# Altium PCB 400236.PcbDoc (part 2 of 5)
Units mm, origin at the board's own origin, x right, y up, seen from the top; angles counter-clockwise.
Board outline 136.53 x 63.5 mm, 4 copper layers (Top Layer, Mid-Layer 1, Mid-Layer 2, Bottom Layer), stack 1.49 mm thick; 344 components, 236 nets, 1364 pads, 1393 vias.
Unrouted connection lines stored in the file: 6.
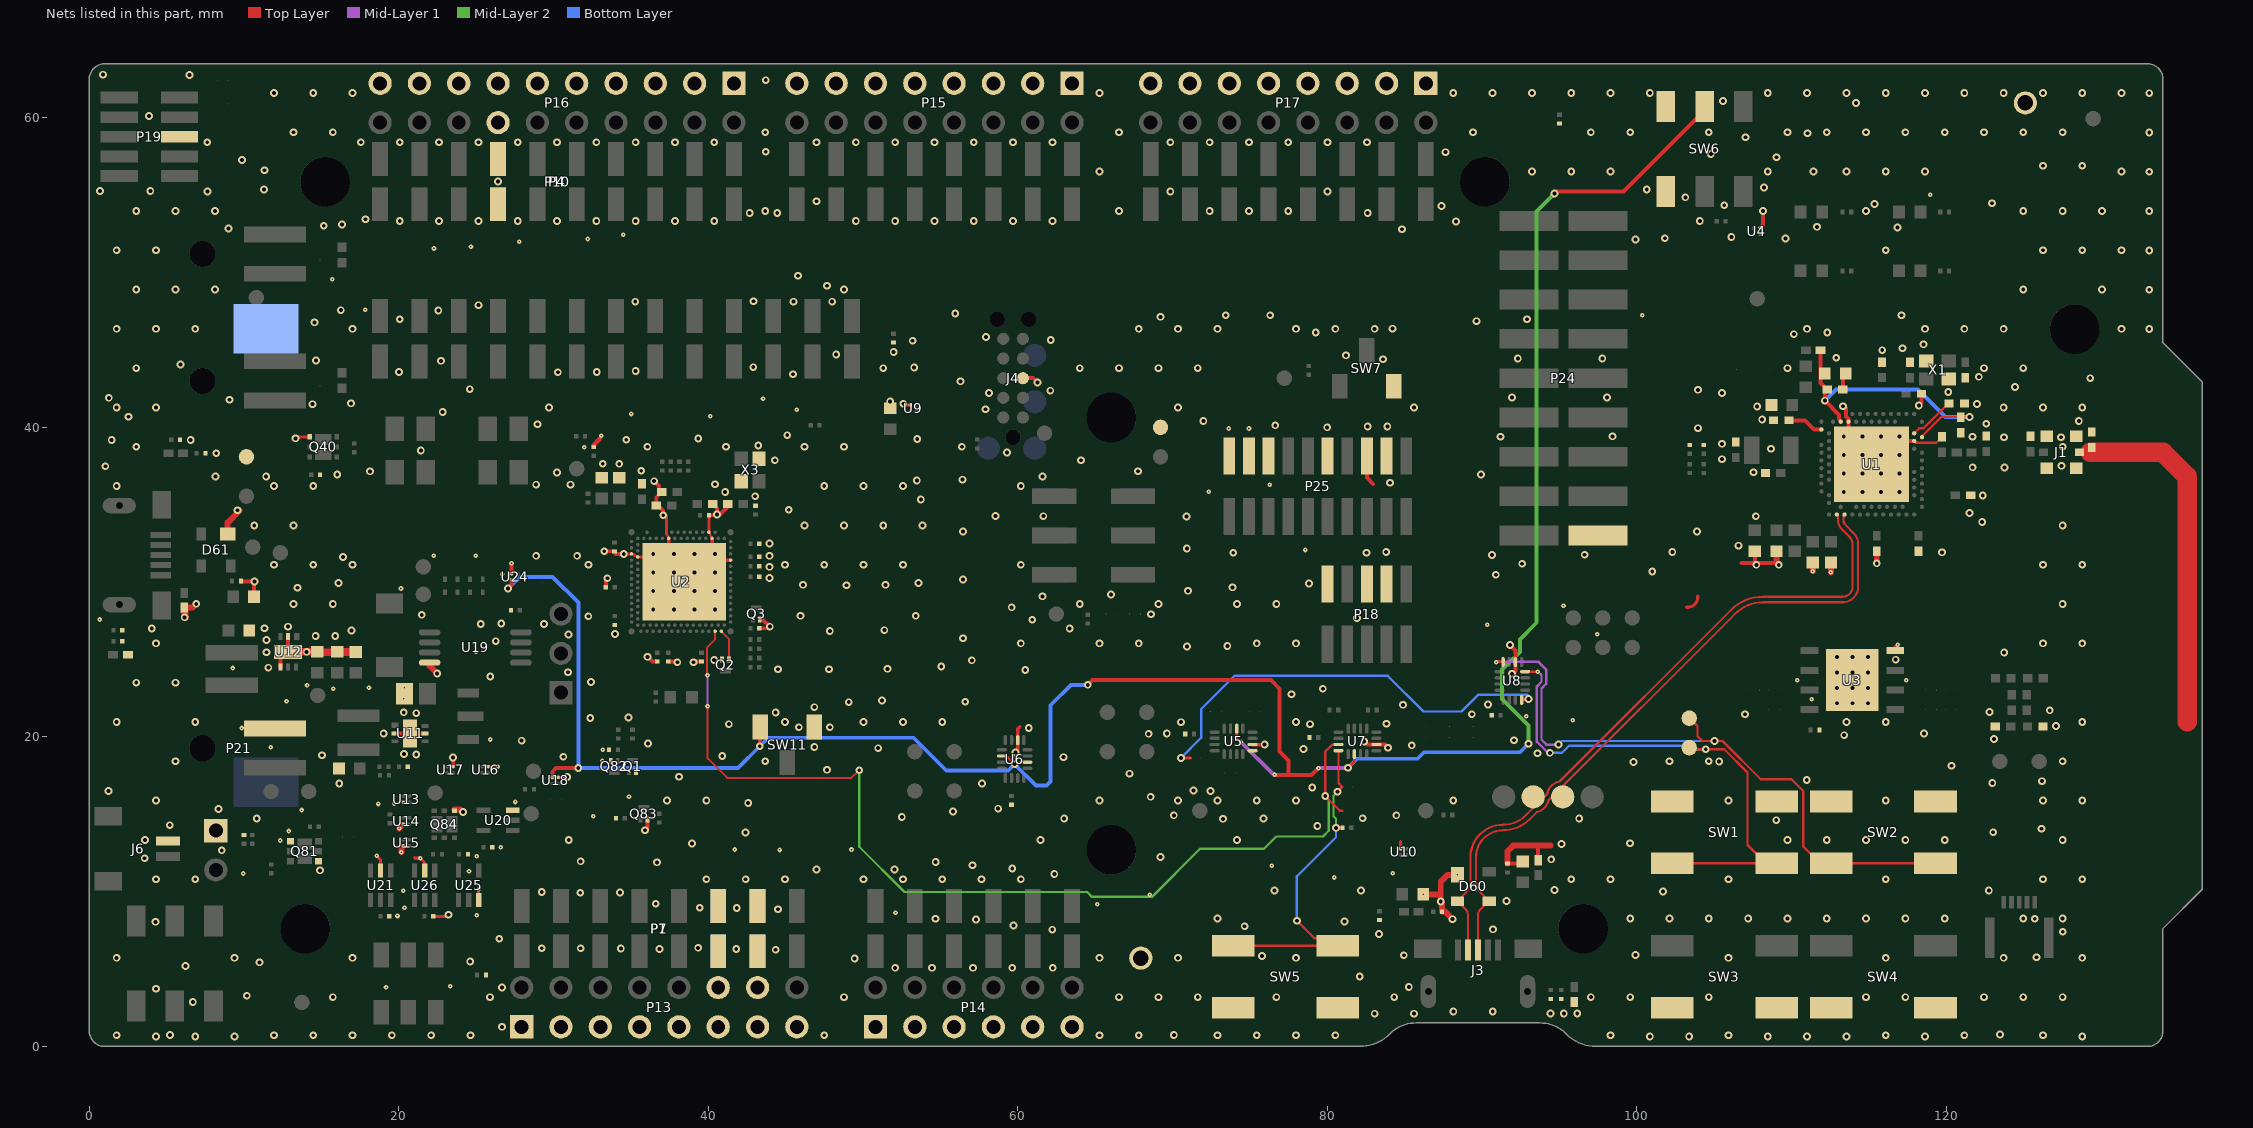
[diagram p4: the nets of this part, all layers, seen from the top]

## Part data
Bat1: library part "Bat Holder L-KLS5-CR2032-23-B1", "Bat Holder CR2032 SMD", Manufacturer="KLS Electronic", Manufacturer Part Number=L-KLS5-CR2032-23-B1, Part number IPS=N.A., Part number NEMS=100500651
C1 C2 C17 C18: library part C0402-12p, "Capacitor, NP0, ±2%", Manufacturer=N.A., Part number IPS=00000002398, Part number NEMS=100200137
C3: library part C0402-0.8p, "Capacitor, NP0, ±5%", Manufacturer=N.A., Part number IPS=00000007782, Part number NEMS=100200116
C4: library part C0402-0.5p, "Capacitor, C0G, ±0.05pF, 50V", Manufacturer=N.A., Part number IPS=00000004293, Part number NEMS=100200112
C5 C7 C8 C12: library part C0402-100n, "Capacitor, X7R, ±10%", Manufacturer=N.A., Part number IPS=00000005296, Part number NEMS=100200184
C6 C20 C38: library part C0603-4µ7-6.3V-X7R, "Capacitor, X7R, ±10%, 6.3V", Manufacturer="Samsung Electro-Mechanics America", Manufacturer Part Number=CL10B475KQ8NQNC, Part number IPS=00000002541, Part number NEMS=100200350, Part number Norautron=N.A., Supplier Part Number 1=1276-2087-1-ND
C9 C10 C13 C22: library part C0402-N.C., "Not mounted", Manufacturer=N.A., Part number NEMS=100200105
C11: library part C0402-100p, "Capacitor, NP0, ±5%", Manufacturer=N.A., Part number IPS=00000002361, Part number NEMS=100200148
C14 C15 C91 C92: library part C0603-1µ0, "Capacitor, X7R, ±10%", Manufacturer=N.A., Part number IPS=00000000616, Part number NEMS=100200271, Part number Norautron=262083409
C16: library part C0402-47n, "Capacitor, X7R, ±10%, 25V", Manufacturer=N.A., Part number IPS=00000003143, Part number NEMS=100200180
C19 C21 C37: library part C0603-4µ7-10V-X7S, "Capacitor, X7S, ±10%, 10V", Manufacturer=N.A., Part number IPS=00000001779, Part number NEMS=100200351, Supplier Part Number 1=445-14258-1-ND
C23: library part C0402-1.2p, "Capacitor, NP0, ±0.1pF", Manufacturer=N.A., Part number IPS=00000005410, Part number NEMS=100200119
C24 C25 C26 C27 C31 C32 C33 C34 C39 C42 C45 C48 C49 C50 C62 C65 C68 C69 C85 C89 C90 C93 C94: library part C0201-100n, "Capacitor, X5R, ±10%", Manufacturer=N.A., Part number IPS="00000001248, 00000002505", Part number NEMS=100200078, Part number Norautron=262071862
C28 C29 C35 C36 C40: library part C0402-1µ0-6.3V-X5R-10%, "Capacitor, X5R, ±10%, 6.3V", Manufacturer=N.A., Part number NEMS=100200498, Part number Norautron=26207137
C30: library part C0201-2n2, "Capacitor, X7R, ±10%, 10V", Manufacturer=N.A., Part number IPS=00000001778, Part number NEMS=100200060, Part number Norautron=26470002
C46 C47: library part C0402-300p, "Capacitor, C0G, ±5%, 50V", Manufacturer=N.A., Part number IPS=00000007788, Part number NEMS=100200155, Supplier Part Number 1=490-3234-1-ND
C51 C52: library part C0201-N.C., "Not mounted", Manufacturer=N.A., Part number NEMS=100200001
C53 C60 C63: library part C0201-10n, "Capacitor, X7R, ±10%", Manufacturer=N.A., Part number IPS=00000003480, Part number NEMS=100200067, Part number Norautron=26621779
C61 C64: library part C0603-10µ, "Capacitor, X5R, ±20%", Manufacturer=N.A., Part number IPS=00000007785, Part number NEMS=100200275
C66 C67: library part C0201-4n7, "Capacitor, X7R, ±10%, 10V", Manufacturer=N.A., Part number IPS=00000001243, Part number NEMS=100200063
C80 C82 C83 C88: library part C0603-10µ-25V-X5R-CL10A106MA8NRNC, "Capacitor, X5R, ±20%, 25V", Manufacturer="Samsung Electro-Mechanics America", Manufacturer Part Number=CL10A106MA8NRNC, Part number IPS=00000009948, Part number NEMS=100200354, Part number Norautron=N.A., Supplier Part Number 1=1276-1869-1-ND
C86: library part C0805-4µ7, "Capacitor, X5R, ±10%, 16V", Manufacturer=N.A., Part number IPS=00000006289, Part number NEMS=100200284
C87: library part C0201-150p-25V-COG-GRM0335C1E151JA01D, "Capacitor, NP0, ±5%, 25V", Manufacturer=N.A., Part number IPS=00000004306, Part number NEMS=100200444
C96: library part C0603-N.C., "Not mounted", Manufacturer=N.A., Part number NEMS=100200195
D60 D61: "Ultra low capacitance double rail-to-rail ESD protection diode", Manufacturer="NXP Semiconductors", Part number IPS=00000009951, Part number NEMS=101300082, Part number Norautron=26313940, Supplier Part Number 1=568-4140-1-ND
D80 D81 D82 D83: "20V schottky barrier diode, Vf 350 mV @ 100 mA, Ir 2.0 µA @ 10 V, If 500 mA", Manufacturer="ON Semiconductor", Part number IPS=00000009952, Part number NEMS=101300131, Part number Norautron=26311081, Supplier Part Number 1=NSR0620P2T5GOSCT-ND
D84: "Diode Schottky Vf=0.45, Vr=40V, If=1A, Ir=1µA", Manufacturer="Good-Ark Semiconductor", Part number IPS=N.A., Part number NEMS=101300212, Supplier Part Number 1=4786-LS14CT-ND
FB60 FB61 FB62 FB63 FB64 FB65: library part FB0402-120R@100M-500mA, "Ferrite Bead, 120 Ohm @ 100MHz, 500mA, 250 mOhm Max", Manufacturer=Murata, Manufacturer Part Number=BLM15AG121SN1D, Part number IPS=00000009954, Part number NEMS=100300099, Part number Norautron=265230631, Supplier Part Number 1=490-1005-1-ND
Fid1 Fid2: library part Fid-Mark, "Fiducial Mark", Manufacturer=N.A., Part number NEMS=100500073
J1: "Coaxial Connector with Switch", Manufacturer=Murata, Part number IPS=00000009955, Part number NEMS=100500400, Part number Norautron=26030338, Supplier Part Number 1=490-4981-1-ND
J2 J3: library part USB-Micro-B-RA-SMD-PiP, "MicroUSB-B-SMT", Manufacturer="Allen Creations Corp.", Manufacturer Part Number=AJU55-BS2111-L, Part number IPS=00000007790, Part number NEMS=100500490, Part number Norautron=N.A.
J4: library part TC2050-IDC-NLFP, "CBL PLUG-OF-NAILS 10-PIN", Manufacturer="Tag-Connect LLC", Part number IPS=N.A., Part number NEMS=100500463, Supplier Part Number 1=TC2050-IDC-NL-ND
J5: library part FPC_05P-0.5mm-RA-SMD, "0.5mm FPC, 5P,Right Angle SMT,Double Contact,H=1.2mm,White, Tin plated", Manufacturer=WCON, Manufacturer Part Number=5141-05RZDNWR03, Part number IPS=N.A., Part number NEMS=100500528
J6: library part SM02B-SRSS-TB, "1.0mm pitch connector side entry SMD", Manufacturer="JST Sales America Inc.", Manufacturer Part Number=SM02B-SRSS-TB(LF)(SN), Part number IPS=00000007791, Part number NEMS=100500383, Part number Norautron=N.A.
L1: library part L0402-4n7-LQG15HS4N7B02D, "Inductor, 700mA, ±0.1nH, 160mR LQG", Manufacturer=Murata, Manufacturer Part Number=LQG15HS4N7B02D, Part number IPS=N.A., Part number NEMS=100300410, Supplier Part Number 1=490-LQG15HS4N7B02DTR-ND
L2 L4: library part L0603-10µ-TDK, "Inductor, 250mA, ±20%, 1.05ohm. -55°C ~ 125°C", Manufacturer="TDK Corporation", Manufacturer Part Number=MLZ1608M100WTD25, Part number IPS=N.A., Part number NEMS=100300079, Part number Norautron=26521771, Supplier Part Number 1=445-175588-1-ND
L3: library part L0402-15n-LQG15HS15NJ02D, "Inductor, 450mA, ±5%,  0.32ohm", Manufacturer=Murata, Manufacturer Part Number=LQG15HS15NJ02D, Part number IPS=N.A., Part number NEMS=100300412, Supplier Part Number 1=490-2625-2-ND
L80: library part VLS3012HBX-4R7M-N, "4.7µH Shielded Wirewound Inductor 2.23A 201 mOhm Max Nonstandard", Manufacturer="TDK Corporation", Part number IPS=N.A., Part number NEMS=100300407, Supplier Part Number 1=445-VLS3012HBX-4R7M-NTR-ND
L81: library part NR3015-4µ7-1.04A-144mOhm, "Ferrite Inductor, Shielded, 1,04A, 144mOhm", Manufacturer="Taiyo Yuden", Manufacturer Part Number=NR3015T4R7M, Part number IPS=00000009960, Part number NEMS=100300145, Part number Norautron=N.A., Supplier Part Number 1=587-1649-1-ND
LED1 LED2 LED3 LED4 LED5: library part "VS 25C7M5", "LED, Green, 0603, 573nm, Vf=2.0V, 24mcd, - 40 to +85°C", Manufacturer="Victory Electronics", Part number IPS="00000001274, 00000009961", Part number NEMS=101400097, Part number Norautron=26313411, Supplier Part Number 1=N.A.
P1 P3 P6: library part "Socket 1x8 SMD", "Socket 1x8, 2.54mm (100mil), SMD", Manufacturer=WCON, Manufacturer Part Number=2171-108MS0CUNR3, Part number IPS=N.A., Part number NEMS=100500412
P2: library part "Socket 1x6 SMD", "Socket 1x6, 2.54mm (100mil), SMD", Manufacturer=WCON, Manufacturer Part Number=2171-106MS0CUNR3, Part number IPS=N.A., Part number NEMS=100500408
P4: library part "Socket 1x10 SMD", "Socket 1x10, 2.54mm (100mil), SMD", Manufacturer=WCON, Manufacturer Part Number=2171-110MS0CUNR3, Part number IPS=N.A., Part number NEMS=100500416
P5: library part "Pin Header 2x3 SMD", "Pin Header 2x3, 2.54mm (100mil) SMD", Manufacturer=WCON, Manufacturer Part Number=1125-1203S0M116CR03, Part number IPS=N.A., Part number NEMS=100500242
P7 P9 P12: library part "Pin List 1x8 SMD, N.C.", "Pin List 1x8, 2.54mm (100mil), SMD", Manufacturer=WCON, Manufacturer Part Number=1125-1108S0M116CR04, Part number IPS=N.A., Part number NEMS=100500330
P8: library part "Pin List 1x6 SMD, N.C.", "Pin List 1x6, 2.54mm (100mil), SMD", Manufacturer=WCON, Manufacturer Part Number=1125-1106S0M116R2, Part number IPS=N.A., Part number NEMS=100500321
P10: library part "Pin List 1x10 SMD, N.C.", "Pin List 1x10, 2.54mm (100mil), SMD", Manufacturer=WCON, Manufacturer Part Number=1125-1110S0M116R2, Part number IPS=N.A., Part number NEMS=100500338
P11: library part "Socket 2x3 SMD, N.C.", "Socket 2x3, 2.54mm (100mil), SMD", Manufacturer=WCON, Manufacturer Part Number=2171-203MS0CUNR3, Part number IPS=N.A., Part number NEMS=100500434
P13 P15 P17: library part "Pin Header 2x8, N.C.", "Pin Header 2x8, 2.54mm (100mil)", Manufacturer=N.A., Part number NEMS=100500270
P14: library part "Pin Header 2x6, N.C.", "Pin Header 2x6, 2.54mm (100mil)", Manufacturer=N.A., Part number NEMS=100500265
P16: library part "Pin Header 2x10, N.C.", "Pin Header 2x10, 2.54mm (100mil)", Manufacturer=N.A., Part number NEMS=100500274
P18 P19: library part "Pin Header 2x5 SMD, 1.27mm, KS", "Pin Header 2x5, 1.27mm (50mil), SMD, Keying Shroud", Manufacturer=WCON, Manufacturer Part Number=3132-10MS0BK00R5, Part number IPS=N.A., Part number NEMS=100500261
P20: library part "Pin List 1x13 SMD", "Pin List 1x13, 2.54mm (100mil), SMD", Manufacturer=WCON, Manufacturer Part Number=1125-1113S0M116CR04, Part number IPS=N.A., Part number NEMS=100500345
P21 P22 P23: library part "Pin List Ang 1x2 SMD, 2.54mm", "Pin List 1x2, 2.54mm (100mil), Right Angled, SMD", Manufacturer=WCON, Manufacturer Part Number=1125B-1102S0Z135CR06, Part number IPS=N.A., Part number NEMS=100500354
P24: library part "Socket 2x9 SMD", "Socket 2x9, 2.54mm (100mil), SMD", Manufacturer=WCON, Manufacturer Part Number=2171-209MS0CUNR3, Part number IPS=N.A., Part number NEMS=100500440
P25: library part "Pin Header 2x10 SMD, 1.27mm, KS, N.C.", "Pin Header 2x10, 1.27mm (50mil), SMD, Keying Shroud", Manufacturer=WCON, Manufacturer Part Number=3132-20MS0BK00R1, Part number IPS=N.A., Part number NEMS=100500279
P26: library part "Socket 1x13 SMD, N.C.", "Socket 1x13, 2.54mm (100mil), SMD", Manufacturer=WCON, Manufacturer Part Number=2171-113MS0CUNR1, Part number IPS=N.A., Part number NEMS=100500422
P27: library part "Pin List 1x2, N.C.", "Pin List 1x2, 2.54mm (100mil)", Manufacturer=N.A., Part number NEMS=100500298
P28: library part "Pin List 1x3, N.C.", "Pin List 1x3, 2.54mm (100mil)", Manufacturer=N.A., Part number NEMS=100500305
Q1 Q2 Q3 Q82 Q83: "N-Channel MOSFET, 20V, 1A, 470mOhm, 400mW", Manufacturer="Rohm Semiconductor", Part number IPS=00000009976, Part number NEMS=101300132, Part number Norautron=26320026, Supplier Part Number 1=RV2C010UNT2LCT-ND
Q40 Q84: library part PMCPB5530X,115, "Mosfet Array N and P-Channel 20V 4A (Ta), 3.4A (Ta) 490mW Surface Mount 6-HUSON-EP (2x2)", Manufacturer=Nexperia, Part number IPS=00000001918, Part number NEMS=101300165, Part number Norautron=N.A., Supplier Part Number 1=1727-1327-1-ND
Q80: "45V NPN high gain power transistor", Manufacturer="Diodes Incorporated", Part number IPS=00000009974, Part number NEMS=101300130, Part number Norautron=N.A., Supplier Part Number 1=FCX690BCT-ND
Q81: "Dual N Ch MOFET, 5.8A, 55mOhm max, 620mW", Manufacturer="Taiwan Semiconductor", Part number IPS=00000001703, Part number NEMS=101300161, Part number Norautron=N.A., Supplier Part Number 1=TSM250N02DCQRFGCT-ND
R1 R2: library part R0201-0R, "Resistor, ±5%, 0.05W", Manufacturer=N.A., Part number IPS=00000003245, Part number NEMS=100100001
R3 R4 R99: library part R0201-10k, "Resistor, ±1%, 0.05W", Manufacturer=N.A., Part number IPS=00000001255, Part number NEMS=100100065, Part number Norautron=26107101
R5 R88 R92 R94: library part R0201-10M, "Resistor, ±1%, 0.05W", Manufacturer=N.A., Part number IPS=00000001426, Part number NEMS=100100105
R6 R26: library part R0201-47k, "Resistor, ±1%, 0.05W", Manufacturer=N.A., Part number IPS=00000001423, Part number NEMS=100100076
R7: library part R0201-560, "Resistor, ±1%, 0.05W", Manufacturer=N.A., Part number NEMS=100100038
R8 R95: library part R0201-100k, "Resistor, ±1%, 0.05W", Manufacturer=N.A., Part number IPS=00000001419, Part number NEMS=100100080, Part number Norautron=26108487
R9: library part R0201-49R9, "Resistor, ±1%, 0.05W", Manufacturer=N.A., Part number NEMS=100100612, Part number Norautron=26107071
R10 R54: library part R0201-N.C., "Not mounted", Manufacturer=N.A., Part number NEMS=100100107
R11 R12 R14 R15 R16 R17 R18 R19: library part R0201-150, "Resistor, ±1%, 0.05W", Manufacturer=N.A., Part number IPS=00000001420, Part number NEMS=100100029
R13: library part R0201-2R2, "Resistor, ±1%, 0.05W", Manufacturer=N.A., Part number NEMS=100100006, Part number Norautron=26470029
R20 R41 R62 R63 R68 R86 R87 R89 R96: library part R0201-1M0, "Resistor, ±1%, 0.05W", Manufacturer=N.A., Part number IPS=00000001418, Part number NEMS=100100093, Part number Norautron=26107108
R40: library part R0201-150k, "Resistor, ±1%, 0.05W", Manufacturer=N.A., Part number IPS=00000001422, Part number NEMS=100100082
R43 R45 R90 R91: library part R0402-N.C., "Not mounted", Manufacturer=N.A., Part number NEMS=100100281
R44 R46: library part R0402-0R, "Resistor, ±5%, 0.063W", Manufacturer=N.A., Part number IPS=00000007128, Part number NEMS=100100109, Supplier Part Number 1=146-9661
R47 R48 R50 R51: library part R0201-220, "Resistor, ±1%, 0.05W", Manufacturer=N.A., Part number IPS=00000000863, Part number NEMS=100100032, Part number Norautron=26107014
R52 R53: library part R0201-4k7, "Resistor, ±1%, 0.05W", Manufacturer=N.A., Part number IPS=00000001706, Part number NEMS=100100061
R69: library part R0201-866, "Resistor, ±1%, 0.05W", Manufacturer=N.A., Part number IPS=00000004368, Part number NEMS=100100042
R82: library part R0201-330k, "Resistor, ±1%, 0.05W", Manufacturer=N.A., Part number IPS=00000001424, Part number NEMS=100100087
R83: library part R0201-820k, "Resistor, ±1%, 0.05W", Manufacturer=N.A., Part number IPS=00000001427, Part number NEMS=100100092
R84: library part R0201-120k, "Resistor, ±1%, 0.05W", Manufacturer=N.A., Part number IPS=00000001425, Part number NEMS=100100081
R85: library part R0201-470k, "Resistor, ±1%, 0.05W", Manufacturer=N.A., Part number IPS=00000001428, Part number NEMS=100100089
R93: library part R0201-1k0, "Resistor, ±1%, 0.05W", Manufacturer=N.A., Part number IPS=00000005786, Part number NEMS=100100043
R97 R98: library part R0201-4R7, "Resistor, ±1%, 0.05W", Manufacturer=N.A., Part number IPS=00000002486, Part number NEMS=100100010
SB1 SB2 SB5 SB6 SB7 SB8 SB10 SB11 SB12 SB13 SB14 SB15 SB16 SB33 SB38 SB40 SB41 SB42 SB50 SB51 SB52 SB53 SB54 SB55 SB56 SB57 SB58 SB60: library part "Solderbridge Shorted", "Shorted Solderbridge", Manufacturer=N.A., Part number NEMS=100500459
SB3 SB4 SB9 SB17 SB18 SB19 SB20 SB21 SB22 SB23 SB24 SB25 SB31 SB32 SB34 SB36 SB37 SB39 SB43 SB44 SB45 SB46 SB47 SB48 SB59 SB80 SB81: Manufacturer=N.A., Part number NEMS=100500458
SW1 SW2 SW3 SW4 SW5: library part Switch-PB-6.2x6.3mm-SMD, "Tactile Switch, SPNO, SMD, 160gf, 6.2x6.3x2.5mm", Manufacturer=Dailywell, Manufacturer Part Number=TS604VM1-025BR-R, Part number IPS=00000007812, Part number NEMS="101500001, 101500133", Part number Norautron=N.A.
SW6 SW8: "Slide Switch DPDT", Manufacturer=Dailywell, Part number IPS=00000004369, Part number NEMS=101500096, Part number Norautron=N.A.
SW7 SW11: library part CJS-1200TA, "SMD slide Switch (ON-ON)", Manufacturer="Copal Electronics Inc", Part number IPS=00000009982, Part number NEMS=101500005, Part number Norautron=26030738, Supplier Part Number 1=563-1021-2-ND
SW9: "Slide Switch DP3T 300mA 6V", Manufacturer=C&K, Part number IPS=00000004321, Part number NEMS=101500099, Part number Norautron=N.A., Supplier Part Number 1=CKN10725CT-ND
SW10: "Slide Switch DPDT J Hook", Manufacturer="Copal Electronics Inc", Part number IPS=00000009983, Part number NEMS=101500003, Part number Norautron=N.A., Supplier Part Number 1=CAS220JTR-ND
TP1 TP2 TP3 TP4 TP5 TP6 TP7 TP8 TP9 TP10 TP11 TP12 TP17 TP18 TP19 TP20 TP21 TP22 TP23 TP24 TP25 TP26 TP27 TP28 TP29 TP30 TP31 TP32 TP33 TP34 TP35 TP36 TP37 TP38 TP39 TP42 TP43 TP44 TP45 TP46 TP47: library part TP_SMD_Ø1.0MM, "1.0mm circular SMD testpad", Manufacturer="Nordic Semiconductor", Manufacturer Part Number=N.A., Part number NEMS=100500475
TP13 TP14 TP15 TP16 TP48 TP49 TP50 TP51: library part TP_SMD_Ø1.5MM, "1.5mm circular SMD testpad", Manufacturer="Nordic Semiconductor", Manufacturer Part Number=N.A., Part number NEMS=100500477
TP40 TP41: library part "Testpoint TH", "Testpoint, through hole", Manufacturer=N.A., Part number NEMS=100500464
U1: library part nRF52840-QIAAF0, "Multi-protocol Bluetooth Low Energy, IEEE 802.15.4, ANT and 2.4GHz proprietary system-on-chip", Manufacturer="Nordic Semiconductor", Part number IPS=80000002377, Part number NEMS=102000222, Part number Norautron=N.A.
U2: library part nRF5340-QKAAD0, "Multi-protocol Bluetooth Low Energy, IEEE 802.15.4, ANT and 2.4GHz proprietary system-on-chip", Manufacturer="Nordic Semiconductor", Part number IPS=N.A., Part number NEMS=102000216, Part number Norautron=NOD26470035
U3: library part MX25R6435FZNIL0, "Ultra low power, 64M-bit, serial multi I/O flash memory", Manufacturer=Macronix, Part number IPS=00000004370, Part number NEMS=101900438, Part number Norautron=N.A.
U4 U9 U10 U13 U14 U15 U16 U17 U18 U24: "1.0 A Load Switch IC with Slew Rate Control Driver in Ultra Small Package", Manufacturer=Toshiba, Manufacturer Part Number=TCK106AG,LF, Part number IPS=00000004390, Part number NEMS=101900575, Part number Norautron=26500627, Supplier Part Number 1=TCK106AGLFTR-ND
U5 U6 U7 U8: "Data / Audio Low-Voltage Dual DPDT Analog Switch", Manufacturer="ON Semiconductor", Part number IPS=00000009986, Part number NEMS=101900422, Part number Norautron=26500608, Supplier Part Number 1=FSA2466UMXCT-ND
U11: library part XC9236D08CER-G, "600mA Driver Transistor Built-In, Synchronous Step-Down DC/DC Converters", Manufacturer="Torex Semiconductor", Part number IPS=00000004325, Part number NEMS=101900207, Part number Norautron=N.A., Supplier Part Number 1=865-XC9236D08CER-G
U12: library part XC9148A50CER-G, "1.4A Driver Transistor Built-In, Multi Functional Step-Up DC/DC Converter", Manufacturer="Torex Semiconductor", Part number IPS=N.A., Part number NEMS=101900670
U19: "Precision very low power CMOS dual operational amplifier", Manufacturer=STMicroelectronics, Part number IPS=00000009991, Part number NEMS=101900442, Part number Norautron=N.A., Supplier Part Number 1=497-8085-1-ND
U20 U25: library part 74LVC1G08GW, "Single 2-Input AND Gate", Manufacturer="NXP Semiconductors", Part number IPS=00000009992, Part number NEMS=101900155, Part number Norautron=N.A., Supplier Part Number 1=568-1580-1-ND
U21 U26: library part 74LVC1G11GW, "Single 3-input AND gate", Manufacturer="NXP Semiconductors", Part number IPS=00000001430, Part number NEMS=101900157, Part number Norautron=N.A., Supplier Part Number 1=568-7757-1-ND
X1 X3: library part XTAL_SMD2016_32MHz_8pF_Golledge_MP12308, "XTAL SMD 2016, 32MHz, Cl=8pF, Tol: ±10ppm, Stab: ±15ppm, -30°C ~ 85°C, ESR: 50ohm max", Manufacturer=Golledge, Manufacturer Part Number=MP12308, Part number IPS=N.A., Part number NEMS=101600118,101600041
X2: library part XTAL_SMD3215_32.768kHz_9pF_NDK, "XTAL SMD 3215, 32.768kHz, 9pF, ±20ppm", Manufacturer=NDK, Manufacturer Part Number=NX3215SA-32.768K-STD-MUA-9, Part number IPS=00000005419, Part number NEMS=101600019, Part number Norautron=N.A.

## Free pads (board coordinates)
  round 3.2 hole 3.2 unplated: 1(13.97,7.62) 1(15.24,55.88) 1(66.04,12.7) 1(66.04,40.64) 1(90.17,55.88) 1(96.52,7.62) 1(128.27,46.355)

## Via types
v1: diameter 0.5, hole 0.25, Top Layer to Bottom Layer, tented both sides, 1166 vias
v2: diameter 0.3, hole 0.1, Top Layer to Mid-Layer 1, tented top, 227 vias

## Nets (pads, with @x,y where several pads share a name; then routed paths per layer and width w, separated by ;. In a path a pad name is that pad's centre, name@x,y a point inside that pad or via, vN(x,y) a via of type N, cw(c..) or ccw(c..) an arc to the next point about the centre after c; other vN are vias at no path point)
ANT: C23.1 J1.3 | length 22.7
  Top Layer w1.27: 129.303,38.391 133.992,38.391 135.551,36.832 135.551,20.99
BOOT/RESET: R54.1 SB43.1 SW5.2 U7.16 | length 22
  Top Layer w0.152: SW5.2@73.917,6.502 SW5.2@79.655,6.502 ; v1(78.029,8.128) 79.153,7.004 79.368,7.004 79.655,6.717 SW5.2@79.655,6.502 ; v1(80.645,16.459) 80.95,16.764 80.95,16.782 80.715,17.016 U7.16@80.715,19.11 U7.16@80.68,19.11 ; SW5.2@80.667,6.502 79.913,6.502 SW5.2@79.655,6.502
  Top Layer w0.203: v1(80.55,14.125) R54.1@80.965,14.125
  Mid-Layer 2 w0.152: v1(80.55,14.125) 80.55,14.716 80.391,14.875 80.391,16.196 80.645,16.45 v1(80.645,16.459)
  Bottom Layer w0.152: v1(78.029,8.128) 78.029,11.004 80.55,13.525 v1(80.55,14.125)
BUTTON1: SW1.2 TP20.1 U8.4 | length 35.3
  Top Layer w0.152: U8.4@92.773,24.222 93.609,24.222 v2@93.624,24.206 ; SW1.2@102.278,11.83 SW1.2@108.331,11.83 ; TP20.1@103.378,19.304 103.48,19.202 v1(104.445,19.202) 105.634,19.202 107.137,17.699 107.137,13.024 SW1.2@108.331,11.83 ; SW1.2@109.707,11.83 SW1.2@109.028,11.83 SW1.2@108.331,11.83
  Mid-Layer 1 w0.152: v2@93.624,24.206 93.828,24.003 93.828,23.562 93.531,23.266 93.531,19.693 94.251,18.974 v1(94.369,18.974)
  Bottom Layer w0.152: v1(94.369,18.974) 95.149,18.974 95.606,19.431 103.454,19.431 103.683,19.202 v1(104.445,19.202)
  other v2: 93.599,24.206
BUTTON2: SW2.2 TP21.1 U8.8 | length 42.9
  Top Layer w0.152: v2@90.887,24.847 U8.8@91.348,24.847 ; TP21.1@103.378,21.234 103.914,20.699 103.914,20.049 104.227,19.736 v1(105.004,19.736) 105.532,19.736 107.995,17.272 109.981,17.272 110.744,16.509 110.744,12.927 111.841,11.83 SW2.2@112.54,11.83 SW2.2@119.29,11.83 SW2.2@119.913,11.83
  Mid-Layer 1 w0.152: v2@90.887,24.847 93.645,24.847 94.132,24.359 94.132,23.436 93.836,23.139 93.836,19.82 94.148,19.507 v1(94.928,19.507)
  Bottom Layer w0.152: v1(94.928,19.507) 95.157,19.736 v1(105.004,19.736)
  other v2: 90.912,24.822
CTS: SB50.1 U8.16 | length 28.9
  Top Layer w0.152: U8.16@92.548,22.397 v1@92.907,22.397 ; v1@93.04,22.53 v1@92.907,22.397 ; v1@93.167,22.479 93.085,22.397 v1@92.907,22.397
  Top Layer w0.203: v1(70.536,18.644) 70.963,18.644 SB50.1@71.138,18.644
  Bottom Layer w0.152: v1(70.536,18.644) 71.839,19.947 71.839,21.794 73.998,23.952 83.887,23.952 86.199,21.641 88.664,21.641 89.756,22.733 92.913,22.733 v1@93.167,22.479
  other v1: 92.989,22.454
D_N: D60.2 J3.2 TP13.1 U1.AD4 | length 44
  Top Layer w0.138: J3.2@89.086,5.985 89.086,8.495 ccw(c88.578,8.495) 88.938,8.855 D60.2@88.402,9.39 88.912,9.899 ccw(c88.114,10.697) 89.242,10.697 89.242,12.23 cw(c91.338,12.23) 91.338,14.326 ccw(c91.338,16.411) 92.813,14.936 94.183,16.307 ; 94.204,16.333 cw(c95.199,16.129) 94.995,17.124 ; 94.998,17.121 106.088,28.211 cw(c108.136,26.162) 108.136,29.06 113.295,29.06 ccw(c113.295,29.693) 113.928,29.693 113.928,32.467 ccw(c113.29,32.467) 113.741,32.918 113.244,33.415 cw(c113.89,34.061) 112.977,34.061 ; U1.AD4@112.914,34.367 112.982,34.299 112.982,34.061
D_P: D60.3 J3.3 TP14.1 U1.AD6 | length 44
  Top Layer w0.138: J3.3@89.734,5.983 89.734,8.495 cw(c90.242,8.495) 89.883,8.855 ; 89.883,8.854 D60.3@90.429,9.4 ; D60.3@90.44,9.39 89.931,9.899 cw(c90.729,10.697) 89.6,10.697 89.6,12.232 cw(c91.338,12.232) 91.338,13.97 ccw(c91.338,16.418) 93.069,14.687 93.522,15.139 ccw(c93.294,16.129) 94.284,15.901 ; 94.284,15.902 106.34,27.958 cw(c108.136,26.162) 108.136,28.702 113.295,28.702 ; 113.295,28.702 ccw(c113.295,29.693) 114.286,29.693 114.286,32.467 ccw(c113.29,32.467) 113.994,33.172 113.498,33.669 cw(c113.89,34.061) 113.335,34.061 113.335,34.289 U1.AD6@113.414,34.367
DEC1: C5.1 U1.C1 | length 2.3
  Top Layer w0.25: C5.1@109.824,40.455 110.851,40.455 111.439,39.867 U1.C1@111.914,39.867
DEC3: C11.1 U1.D23 | length 3
  Top Layer w0.152: U1.D23@117.914,39.617 117.919,39.617 118.244,39.942 118.514,39.942 120.114,41.542 C11.1@120.164,41.542
DEC4_6: C10.2 C15.2 C16.1 L3.1 U1.B5 U1.E24 | length 19.2
  Top Layer w0.15: U1.E24@118.414,39.367 118.414,39.423 119.657,40.667 v1(121.478,40.667)
  Top Layer w0.25: L3.1@111.864,44.992 111.864,42.867 112.139,42.592 v1(112.139,41.729) 113.064,40.805 113.064,40.544 113.164,40.444 U1.B5@113.164,40.367
  Bottom Layer w0.25: v1(112.139,41.729) 112.852,42.443 118.161,42.443 119.937,40.667 v1(121.478,40.667)
GND: Bat1.2 C1.2 C2.2 C3.1 C4.1 C5.2 C6.2 C7.2 C8.2 C9.2 C10.1 C11.2 C12.2 C13.2 C14.2 C15.1 C16.2 C17.1 C18.1 C19.2 C20.2 C21.2 C22.2 C23.2 C24.2 C25.2 C26.2 C27.2 C28.2 C29.1 C30.2 C31.2 C32.2 C33.2 C34.2 C35.1 C36.1 C37.2 C38.2 C39.2 C40.1 C42.1 C45.1 C46.2 C47.1 C48.1 C49.1 C50.1 C51.1 C52.1 C53.1 C60.1 C61.1 C62.1 C63.2 C64.1 C65.1 C66.1 C67.1 C68.1 C69.1 C80.1 C82.1 C83.1 C85.1 C86.1 C88.1 C89.1 C90.1 C91.1 C92.1 C93.1 C94.1 C96.1 D60.1 D61.1 FB62.2 FB63.2 FB64.2 FB65.2 J1.2 J4.3 J6.1 P1.6 P1.7 P4.7 P7.6 P7.7 P10.7 P13.1 P13.3 P13.5 P13.7 P13.9 P13.11 P13.12 P13.13 P13.14 P13.15 P14.1 P14.3 P14.5 P14.7 P14.9 P14.11 P15.1 P15.3 P15.5 P15.7 P15.9 P15.11 P15.13 P15.15 P16.1 P16.3 P16.5 P16.7 P16.9 P16.11 P16.13 P16.14 P16.15 P16.17 P16.19 P17.1 P17.3 P17.5 P17.7 P17.9 P17.11 P17.13 P17.15 P18.3 P18.5 P18.9 P19.5 P21.1 P24.18 P25.3 P25.5 P25.9 P25.15 P25.17 P25.19 P27.1 Q1.2 Q2.2 Q3.2 Q40.1 Q81.1 Q81.4 Q82.2 Q83.2 Q84.1 R9.2 R10.2 R20.2 R26.2 R40.2 R62.1 R63.1 R69.1 R84.1 R85.2 R88.2 R92.2 R94.2 SB32.1 SW1.1 SW2.1 SW3.1 SW4.1 SW5.1 SW6.1 SW6.4 SW7.1 SW11.3 TP12.1 TP39.1 TP40.1 TP41.1 U1.74 U1.B7 U1.F23 U2.104 U2.A25 U2.B12 U2.B26 U2.G1 U2.H2 U2.J31 U3.4 U3.9 U4.B1 U5.5 U5.6 U6.6 U7.6 U8.6 U9.B1 U10.B1 U11.2 U11.5 U11.7 U12.2 U12.4 U12.7 U13.B1 U14.B1 U15.B1 U16.B1 U17.B1 U18.B1 U19.4 U20.3 U21.2 U24.B1 U25.3 U26.2 X1.2 X1.4 X3.2 X3.4 | length 86.2
  Top Layer w0.145: U1.F23@117.914,39.117 118.019,39.012 119.335,39.012 C3.1@119.715,39.393
  Top Layer w0.165: U2.A25@40.039,33.227 U2.B26@40.239,32.827
  Top Layer w0.187: v1(34.539,31.827) U2.G1@35.039,31.827 U2.H2@35.439,31.627 U2.104@36.139,31.627 ; v1@37.225,34.375 37.308,34.292 37.308,33.101 ; 37.308,33.097 U2.B12@37.439,32.827
  Top Layer w0.2: U2.A25@40.039,33.227 C39.2@40.039,34.323
  Top Layer w0.203: v1@13.284,39.385 Q40.1@14.168,39.385 ; v2(18.567,12.319) 18.821,12.065 U21.2@18.821,11.364 ; 21.006,12.217 21.057,12.167 v2(21.387,12.167) 21.666,11.887 U26.2@21.666,11.364 ; C94.1@22.231,8.407 23.114,8.407 v1(23.216,8.509) ; U17.B1@23.517,18.082 v1@23.517,18.691 ; U25.3@25.161,9.464 v2(25.161,10.17) ; U16.B1@25.778,18.082 v2(26.387,18.082) ; U18.B1@30.319,17.386 30.859,17.386 v1(30.884,17.412) ; C92.1@51.75,41.225 v1(51.75,41.675) ; v1@52.669,41.456 U9.B1@53.044,41.456 ; U10.B1@84.725,12.775 84.725,13.225 ; 103.207,28.382 ccw(c103.276,29.032) 103.927,29.1
  Top Layer w0.225: U2.104@37.039,31.427 U2.104@38.439,30.027 U2.104@38.734,30.027 ; U2.104@37.439,31.427 U2.B12@37.439,32.827 ; U2.104@39.839,31.427 U2.104@40.239,31.427 ; U2.B26@40.239,32.827 U2.104@40.239,31.427 ; U2.J31@41.439,31.427 U2.104@40.239,31.427
  Top Layer w0.229: U5.6@75.157,19.507 v1(75.946,19.507)
  Top Layer w0.25: U12.4@12.35,24.475 U12.7@12.35,25.125 ; U12.7@12.85,25.45 U12.2@12.85,26.425 ; U11.2@19.751,20.218 U11.7@20.726,20.218 U11.5@21.701,20.218 ; U24.B1@27.283,30.553 v2(27.283,31.22) ; v1(33.275,32) 33.455,32 33.457,32.002 33.871,32.002 C24.2@33.881,31.992 ; C25.2@33.379,29.677 33.379,30.154 v1(33.475,30.25) ; C24.2@33.939,31.992 C24.2@33.881,31.992 ; v1(34.539,31.827) 34.046,31.827 C24.2@33.881,31.992 ; v1(36.075,25.175) 36.385,24.865 R10.2@36.7,24.865 ; v1(36.5,36.525) 36.814,36.211 36.814,35.957 36.939,35.832 C36.1@36.989,35.832 36.639,35.482 C40.1@36.639,35.052 ; C40.1@36.639,34.957 C40.1@36.639,35.052 ; v1@37.064,34.477 37.064,34.627 C40.1@36.639,35.052 ; C27.2@37.415,24.867 37.958,24.867 v1(38,24.825) ; v1(39.05,24.825) 39.092,24.867 C31.2@39.564,24.867 ; C39.2@40.039,34.323 40.51,34.323 v1(40.564,34.377) ; C28.2@40.289,35.052 40.564,34.777 v1(40.564,34.377) ; C29.1@41.264,35.052 41.264,34.89 40.75,34.377 v1(40.564,34.377) ; R20.2@43.285,27.025 43.875,27.025 v1(43.975,27.125) 43.5,27.6 Q3.2@43.325,27.6 ; v1(82.372,19.71) 82.572,19.51 U7.6@83.165,19.51 83.715,19.51 v1(83.922,19.304) ; P25.5@82.55,38.145 82.55,36.754 82.956,36.347 ; U4.B1@107.944,52.881 107.948,52.881 108.15,53.083 v1(108.15,53.975) v1@108.15,53.997 ; v1@113.506,41.26 113.506,40.699 113.664,40.541 U1.B7@113.664,40.367 U1.74@113.664,39.117 ; U1.74@115.164,37.617 116.664,39.117 U1.F23@117.914,39.117
  Top Layer w0.254: C65.1@9.8,30.074 9.8,30.059 9.808,30.051 9.823,30.051 v1(10.675,30.05) ; C64.1@10.647,29.058 v1@10.647,30.048 ; v1(35.916,13.97) 36.064,14.119 Q83.2@36.064,14.687 ; v1(59.842,18.999) 59.992,19.148 U6.6@59.992,19.792 59.992,20.52 60.122,20.65 ; J4.3@60.325,43.18 60.995,43.18 v1(61.275,42.9) ; C62.1@91.632,11.817 92.35,11.817 92.544,12.011 C61.1@92.544,12.032 ; v1(91.796,25.933) 92.148,25.581 U8.6@92.148,24.847 92.148,24.254 v1@91.973,24.079 ; FB62.2@93.614,12.033 93.614,12.979 ; 106.756,31.242 v1@107.613,31.242 ; C6.2@107.613,31.992 v1@107.613,31.242 ; v1@107.664,31.117 107.613,31.168 v1@107.613,31.242 ; v1@109.093,31.242 109.039,31.242 v1@107.613,31.242 ; C16.2@113.301,42.443 113.301,43.294 C15.1@113.489,43.481 ; U3.4@116.689,25.578 116.689,25.808 v2(116.84,25.959) ; v1(118.214,41.417) 118.389,41.592 C12.2@118.389,42.167
  Top Layer w0.3: R88.2@32.588,38.741 32.588,38.862 32.995,39.268
  Top Layer w0.381: FB63.2@6.164,28.337 FB63.2@6.147,28.354 6.668,28.354 v1(6.914,28.6) ; D61.1@8.944,33.105 8.944,33.844 v1@9.725,34.625 ; v2(20.028,14.097) U14.B1@20.237,14.307 ; v2(20.168,12.548) 20.168,12.827 U15.B1@20.231,12.89 ; U19.4@21.993,24.806 21.993,24.591 v1(22.479,24.105) ; Q84.1@23.601,15.301 v1@23.967,15.301 ; v2(86.197,9.83) 87.32,9.83 87.325,9.825 ; v1(88.087,8.23) 87.605,8.712 C60.1@87.407,8.712 87.407,9.291 v1(87.325,9.373) 87.325,9.825 ; v2(88.402,11.09) 87.772,11.09 87.325,10.643 87.325,9.825 ; C62.1@91.632,11.817 91.632,12.613 91.999,12.979 93.614,12.979 94.412,12.979 ; C19.2@109.014,31.992 109.014,31.267 109.039,31.242 v1(109.164,31.117) ; v2@111.364,30.709 C20.2@111.364,31.267 ; v2@112.539,30.632 C21.2@112.539,31.267 ; C7.2@115.49,31.992 115.49,31.221 v1(115.494,31.217)
  Top Layer w0.5: v1(6.164,27.725) FB63.2@6.164,28.337 ; U12.7@12.87,25.47 12.9,25.5 v1(14.05,25.5) C82.1@14.725,25.5 ; C82.1@14.612,25.47 C83.1@15.918,25.47 ; C83.1@15.918,25.49 C96.1@17.215,25.49
  other v1: 4.312,0.647 6.852,0.647 9.392,0.647 100.832,0.647 103.372,0.647 108.452,0.647 110.992,0.647 113.532,0.647 118.612,0.647 128.772,0.647 1.772,0.723 11.932,0.723 14.472,0.723 17.012,0.723 19.552,0.723 22.092,0.723 24.632,0.723 47.492,0.723 65.272,0.723 67.812,0.723 72.892,0.723 75.432,0.723 77.972,0.723 80.512,0.723 98.292,0.723 105.912,0.723 116.072,0.723 121.152,0.723 126.232,0.723 5.223,0.737 70.079,0.737 123.463,0.774 26.67,1.27 83.052,2.12 85.592,2.12 94.412,2.134 95.275,2.134 96.139,2.134 88.138,2.261 90.678,2.261 6.696,2.87 15.742,3.187 25.902,3.187 48.762,3.187 66.542,3.187 69.082,3.187 71.622,3.187 76.702,3.187 84.322,3.187 97.022,3.187 99.562,3.187 104.642,3.187 114.802,3.187 117.342,3.187 122.422,3.187 124.962,3.187 127.502,3.187 10.185,3.277 4.309,3.734 26.67,3.81 85.261,3.847 82.093,4.521 52.07,5.08 54.458,5.08 57.099,5.08 59.639,5.08 62.255,5.08 6.214,5.207 10.998,5.436 24.613,5.486 49.454,5.69 1.772,5.727 9.392,5.727 17.012,5.727 65.272,5.727 70.352,5.727 77.972,5.727 105.912,5.727 116.072,5.727 123.692,5.727 128.772,5.727 125.806,5.766 75.768,5.842 84.938,5.893 99.898,5.918 44.348,6.248 36.85,6.3 41.808,6.299 34.35,6.325 29.235,6.35 31.75,6.35 39.345,6.375 26.492,6.96 83.337,7.264 127.508,7.417 62.225,7.55 90.703,7.569 74.651,7.772 59.725,7.825 4.283,8.052 81.102,8.077 57.3,8.2 54.675,8.25 72.892,8.267 99.562,8.267 102.102,8.267 104.642,8.267 107.182,8.267 109.722,8.267 112.262,8.267 114.802,8.267 117.342,8.267 119.882,8.267 124.962,8.267 125.705,8.255 127.502,8.267 44.501,8.865 41.834,8.941 39.446,8.966 36.6,9.225 91.567,9.398 31.725,9.931 34.3,9.95 29.235,9.982 101.676,10.008 76.581,10.084 82.169,10.084 122.733,10.084 94.666,10.109 4.312,10.807 6.852,10.807 39.872,10.807 42.412,10.807 44.952,10.807 50.032,10.807 52.572,10.807 55.112,10.807 57.652,10.807 60.192,10.807 95.752,10.807 98.292,10.807 105.912,10.807 116.072,10.807 126.232,10.807 128.772,10.807 62.357,11.151 14.91,11.379 46.99,11.43 52.032,11.43 59.639,11.506 57.074,11.709 36.678,11.897 54.686,11.913 31.75,11.963 94.463,12.09 3.581,12.167 69.215,12.243 8.56,12.675 95.123,13.081 38.938,13.117 99.543,13.132 3.607,13.335 30.982,13.347 61.462,13.347 74.162,13.347 109.722,13.347 112.262,13.347 114.802,13.347 117.342,13.347 119.882,13.347 127.502,13.347 42.4,13.825 123.012,13.843 126.136,14.072 79.35,14.249 5.207,14.3 109,14.625 73.254,14.707 10.82,14.732 62.992,14.732 75.87,14.732 82.275,14.75 96.266,14.732 52.502,14.834 70.079,14.935 84.455,14.935 24.145,15.149 55.804,15.189 8.357,15.342 58.725,15.367 42.575,15.725 4.312,15.887 37.332,15.887 39.872,15.887 65.272,15.887 70.352,15.887 72.892,15.887 75.432,15.887 77.972,15.887 88.132,15.887 105.912,15.887 116.072,15.887 126.232,15.887 128.772,15.887 68.58,16.129 1.245,16.51 72.441,16.51 71.349,16.535 79.019,16.739 16.154,16.993 57.683,16.993 122.961,17.018 126.162,17.145 110.973,17.221 38.1,17.425 67.208,17.628 47.675,17.875 120.32,18.136 99.775,18.375 5.582,18.427 43.682,18.427 102.102,18.427 104.642,18.427 105.308,18.415 127.502,18.427 23.499,18.673 62.941,18.694 30.632,18.72 40.9,18.775 15.037,18.821 21.133,18.872 20.345,18.898 93.575,18.95 78.461,19.228 50.975,19.275 46.85,19.35 85.446,19.456 36.1,19.575 27.94,19.761 92.05,19.787 123.063,19.863 113.386,20.117 68.45,20.2 19.025,20.218 69.625,20.225 118.542,20.218 60.706,20.574 45.85,20.625 47.85,20.625 127.076,20.701 41.325,20.825 78.867,20.828 83.82,20.853 1.772,20.967 6.852,20.967 44.952,20.967 50.032,20.967 52.572,20.967 55.112,20.967 70.536,20.955 77.972,20.967 113.532,20.967 116.072,20.967 128.772,20.967 32.375,21.225 34.85,21.25 89.332,21.463 106.985,21.463 21.133,21.539 44.35,21.575 20.32,21.59 122.784,21.615 126.67,21.717 46.85,21.925 84.887,22.073 90.373,22.098 112.919,22.173 113.919,22.173 114.919,22.173 49.075,22.25 56.6,22.275 51.225,22.35 77.673,22.758 79.705,23.114 112.919,23.173 113.919,23.173 114.919,23.173 3.042,23.507 5.582,23.507 32.425,23.55 25.908,23.901 91.923,24.079 112.919,24.173 113.919,24.173 114.919,24.173 30.937,24.181 60.475,24.325 44.5,24.375 47.8,24.375 51.575,24.4 11.575,24.475 55.05,24.55 57.025,24.95 40.375,24.975 116.713,24.994 112.919,25.173 113.919,25.173 114.919,25.173 11.45,25.475 123.723,25.451 70.925,25.85 73.533,25.883 4.312,26.047 60.192,26.047 65.272,26.047 67.812,26.047 75.432,26.047 77.972,26.047 126.232,26.047 128.772,26.047 26.264,26.187 11.453,26.262 56.45,26.375 14.628,26.516 15.898,26.516 30.963,26.619 33.975,26.65 47.85,26.85 16.95,26.875 51.375,26.9 4.039,27 11.326,27.024 63.348,27 12.85,27.125 25.298,27.305 29.388,27.305 26.619,27.331 60.925,27.575 81.915,27.686 32.25,27.8 45.95,27.825 53.4,27.825 21.488,27.889 68.6,27.925 36.439,28.227 37.772,28.227 39.105,28.227 40.439,28.227 59.6,28.375 13.202,28.587 15.742,28.587 64.002,28.587 69.082,28.587 74.162,28.587 76.702,28.587 127.502,28.587 61.595,29.083 66.015,29.21 36.439,29.427 37.772,29.427 39.105,29.427 40.439,29.427 70.993,29.439 13.452,29.642 73.863,29.667 48.925,29.8 46.125,29.825 51.45,29.825 78.816,29.921 16.104,29.947 53.575,29.95 56.45,30.175 43.95,30.275 90.881,30.48 36.439,30.627 37.772,30.627 39.105,30.627 40.439,30.627 100.99,30.683 43.955,30.992 11.932,31.127 14.472,31.127 17.012,31.127 32.252,31.127 44.952,31.127 47.492,31.127 50.032,31.127 52.572,31.127 60.192,31.127 107.714,31.117 126.232,31.127 128.772,31.127 92.583,31.191 16.4,31.625 28.875,31.7 31.525,31.7 43.95,31.7 90.627,31.75 96.622,31.775 36.439,31.827 37.772,31.827 39.105,31.827 40.439,31.827 73.914,31.902 82.525,31.902 119.71,31.928 83.795,31.953 102.286,31.953 70.917,32.182 106.553,32.36 43.95,32.5 56.45,33.275 103.886,33.274 10.662,33.667 13.202,33.667 46.222,33.667 48.762,33.667 51.302,33.667 53.842,33.667 127.502,33.667 122.301,33.884 70.891,34.239 107.68,34.258 58.55,34.275 61.646,34.265 37.089,34.327 121.488,34.468 9.575,34.65 45.2,34.675 53.731,35.335 43.025,35.55 122.339,35.592 41.089,35.827 113.364,35.817 114.564,35.817 115.764,35.817 116.964,35.817 1.772,36.207 11.932,36.207 14.472,36.207 47.492,36.207 50.032,36.207 52.572,36.207 60.192,36.207 28.875,36.3 31.1,36.3 40.425,36.325 84.049,36.424 53.475,36.575 56.425,36.625 8.153,36.83 11.43,36.83 61.595,36.83 89.925,36.95 16.027,36.957 113.364,37.017 114.564,37.017 115.764,37.017 116.964,37.017 30.226,37.084 107.528,37.103 18.136,37.16 67.759,37.17 35.664,37.202 121.689,37.417 123.739,37.416 1.041,37.49 127.422,37.517 33.175,37.65 34.247,37.647 44.3,37.875 64.075,37.875 105.486,37.948 113.364,38.217 114.564,38.217 115.764,38.217 116.964,38.217 8.204,38.329 59.3,38.375 21.425,38.5 108.664,38.617 3.042,38.747 36.062,38.747 41.142,38.747 46.222,38.747 48.762,38.747 56.382,38.747 127.502,38.747 43.225,38.825 105.486,38.938 1.448,39.192 6.553,39.192 34.7,39.2 53.5,39.25 39.35,39.275 13.335,39.294 123.714,39.367 127.397,39.367 91.186,39.395 113.364,39.417 114.564,39.417 115.764,39.417 116.964,39.417 121.681,39.395 98.425,39.421 45.1,39.5 103.95,39.95 79.985,40.005 82.601,40.056 83.871,40.056 76.632,40.132 28.956,40.206 122.57,40.234 71.984,40.411 128.549,40.411 108.087,40.506 2.54,40.691 22.835,40.996 57.912,41.173 1.772,41.287 4.312,41.287 29.712,41.287 70.352,41.287 85.592,41.287 123.692,41.287 126.232,41.287 128.772,41.287 107.764,41.342 113.313,41.368 14.427,41.504 52.6,41.525 121.964,41.517 16.916,41.554 9.068,41.783 1.27,41.91 91.923,41.935 98.069,41.935 58.141,42.215 105.486,42.215 120.114,42.292 62.1,42.375 103.95,42.425 24.587,42.469 124.426,42.617 56.3,42.975 129.286,43.18 122.089,43.267 45.466,43.434 30.277,43.561 20.015,43.586 32.791,43.586 35.306,43.637 3.042,43.827 51.302,43.827 64.002,43.827 66.542,43.827 69.082,43.827 71.622,43.827 109.722,43.827 122.422,43.827 124.962,43.827 53.3,43.875 42.901,43.891 5.893,44.069 22.733,44.298 14.65,44.325 83.591,44.399 92.304,44.45 97.765,44.45 112.878,44.501 81.204,44.653 48.26,44.704 51.975,44.875 115.845,44.992 117.164,45.117 118.516,45.364 53.2,45.6 62.125,45.65 57.937,45.847 110.134,46.025 79.248,46.126 112.293,46.126 1.772,46.367 4.312,46.367 6.852,46.367 17.012,46.367 67.812,46.367 70.352,46.367 72.892,46.367 77.972,46.367 80.512,46.367 83.052,46.367 110.992,46.367 118.612,46.367 121.152,46.367 123.692,46.367 131.312,46.367 133.096,46.355 84.201,46.38 14.554,46.787 89.637,46.863 20.066,46.99 92.888,46.99 69.215,47.142 73.431,47.244 76.302,47.244 117.094,47.244 55.956,47.356 22.555,47.549 16.256,47.574 25.15,47.9 35.275,48.125 45.5,48.125 48,48.125 42.925,48.15 3.042,48.907 5.582,48.907 8.122,48.907 48.762,48.907 124.962,48.907 130.042,48.907 133.096,48.895 47.675,49.15 45.8,49.8 1.772,51.447 4.312,51.447 116.072,51.447 126.232,51.447 128.772,51.447 131.312,51.447 133.096,51.435 99.898,52.146 109.601,52.197 101.803,52.222 106.096,52.299 84.825,52.8 9,52.85 116.84,52.908 111.633,52.959 15.15,53.025 16.332,53.111 88.3,53.3 20.066,53.34 22.606,53.34 25.146,53.34 27.686,53.34 30.226,53.34 32.766,53.34 35.306,53.34 37.846,53.34 40.386,53.34 49.53,53.34 52.07,53.34 54.61,53.34 57.15,53.34 59.69,53.34 62.23,53.34 104.064,53.34 17.85,53.45 42.672,53.848 44.45,53.848 82.601,53.858 3.042,53.987 5.582,53.987 8.122,53.987 43.682,53.987 66.542,53.987 72.39,53.975 74.93,53.975 77.47,53.975 114.802,53.987 124.962,53.987 127.502,53.987 130.042,53.987 133.096,53.975 87.376,54.305 105.639,54.356 115.341,54.432 122.936,54.483 46.99,54.61 103.124,54.864 7.645,55.245 69.85,55.245 80.01,55.245 0.7,55.275 3.95,55.275 11.3,55.375 100.635,55.372 108.204,55.499 26.416,55.89 65.272,56.527 93.212,56.527 95.752,56.527 98.292,56.527 108.452,56.527 113.532,56.527 116.072,56.527 118.612,56.527 131.312,56.527 133.096,56.515 111.404,56.54 11.328,56.617 126.232,56.908 128.772,56.908 9.875,57.275 109.017,57.455 104.775,57.658 87.63,57.785 43.713,57.81 7.625,58.425 17.551,58.42 20.066,58.42 22.606,58.42 25.146,58.42 27.686,58.42 30.226,58.42 32.766,58.42 35.306,58.42 37.846,58.42 40.386,58.42 46.99,58.42 49.53,58.42 52.07,58.42 54.61,58.42 57.15,58.42 59.69,58.42 62.23,58.42 69.85,58.42 72.39,58.42 74.93,58.42 77.47,58.42 80.01,58.42 82.55,58.42 107.01,58.75 111.023,59.004 13.202,59.067 15.742,59.067 43.682,59.067 66.542,59.067 89.402,59.067 97.022,59.067 99.562,59.067 104.642,59.067 109.722,59.067 112.262,59.067 114.802,59.067 117.342,59.067 119.882,59.067 122.422,59.067 124.962,59.067 127.502,59.067 133.096,59.055 3.861,60.122 114.144,60.957 105.562,61.087 11.932,61.607 14.472,61.607 17.012,61.607 65.272,61.607 88.132,61.607 90.672,61.607 93.212,61.607 95.752,61.607 98.292,61.607 100.832,61.607 108.452,61.607 110.992,61.607 113.532,61.607 116.072,61.607 118.612,61.607 121.152,61.607 123.692,61.607 126.232,61.607 128.772,61.607 131.312,61.607 133.096,61.595 43.713,62.433 6.477,62.763 0.889,62.789
  other v2: 19.177,3.835 23.325,3.886 19.914,8.433 25.044,8.484 52.095,8.636 20.371,8.966 65.126,9.195 68.529,9.804 20.295,10.058 80.442,10.922 9.957,11.176 84.226,11.201 24.536,11.328 76.403,11.684 25.044,12.294 44.625,12.7 41.7,12.725 49.25,12.725 26.594,12.878 12.344,13.31 12.903,13.919 32.563,14.884 13.741,15.277 18.669,15.672 19.71,15.697 27.534,15.799 34.874,16.129 33.15,18.45 33.175,19.175 11.735,19.329 25.908,19.837 9.855,20.574 95.86,21.082 92.837,21.336 12.75,22.3 111.303,22.428 20.32,22.454 15.775,23.125 18.075,23.175 20.345,23.165 14.075,23.35 110.363,23.673 117.399,23.673 9.275,24.45 24.994,25.502 97.434,26.634 90.322,27.254 0.686,27.584 95.25,28.473 20.142,29.591 26.68,30.505 112.522,30.632 111.354,30.709 22.25,31.699 24.975,31.7 78.562,32.08 72.339,35.839 76.276,36.297 31.979,38.71 33.071,39.472 73.635,39.929 74.93,39.929 40.132,40.716 35.027,40.869 45.72,41.148 43.536,41.859 100.33,47.244 17.831,47.6 15.697,49.581 22.276,51.562 24.663,51.664 27.788,51.994 32.207,52.172 34.493,52.451 118.948,55.042
I\F\_\O\F\F\: SW6.2 SW11.1 U5.10 U6.2 U6.10 U7.2 U18.B2 U24.B2 | length 153.4
  Top Layer w0.152: U6.10@58.967,18.767 59.26,18.767 v1@59.66,18.367 ; v1@59.792,18.367 U6.2@60.617,18.367 ; U5.10@74.132,20.532 74.147,20.518 74.147,19.928 v2(74.4,19.675) ; v1(81.331,18.009) 81.74,18.418 U7.2@81.74,18.885
  Top Layer w0.25: v1(27.051,29.591) 27.283,29.823 U24.B2@27.283,30.153
  Top Layer w0.254: U18.B2@29.919,17.386 29.919,17.752 30.166,17.999 v1(31.6,18) v1(31.6,18) ; v1(43.325,19.4) 43.35,19.425 SW11.1@43.35,20.65 ; v1(64.516,23.368) 64.823,23.675 76.35,23.675 76.913,23.112 76.913,19.048 77.495,18.466 77.495,17.533 ; v2(76.6,17.55) 76.617,17.533 77.495,17.533 ; v2(79.426,17.983) 78.976,17.533 77.495,17.533 ; v1(94.666,55.118) 94.793,55.245 99.129,55.245 SW6.2@104.369,60.484
  Mid-Layer 1 w0.254: v2(74.4,19.675) 76.507,17.568 76.582,17.568 v2(76.6,17.55) ; v2(79.426,17.983) 81.305,17.983 v1(81.331,18.009)
  Mid-Layer 2 w0.254: v1(92.989,19.558) 92.989,20.752 91.288,22.454 91.288,24.359 92.431,25.502 92.431,26.309 93.497,27.376 93.497,53.95 v1(94.666,55.118)
  Bottom Layer w0.254: v1(27.051,29.591) 27.805,30.345 29.929,30.345 31.6,28.674 v1(31.6,18) 41.925,18 v1(43.325,19.4) 43.875,19.95 53.25,19.95 55.375,17.825 59.379,17.825 v1(59.792,18.237) 61.163,16.866 61.849,16.866 62.103,17.12 62.103,22.046 63.425,23.368 v1(64.516,23.368) ; v1(81.331,18.009) 81.915,18.593 85.827,18.593 86.245,19.011 92.443,19.011 v1(92.989,19.558)
IMCU_BOOT: SB46.2 U2.AL27 U7.15 | length 65.3
  Top Layer w0.125: v2(39.95,21.975) 39.95,18.614 41.214,17.35 49.25,17.35 v1(49.75,17.85) ; v2(39.95,23.975) 39.901,24.024 39.901,25.776 40.439,26.314 U2.AL27@40.439,26.827
  Top Layer w0.152: v1(79.858,16.18) v1@79.865,16.172 ; v1@79.916,16.172 v1@80.035,16.172 ; U7.15@80.715,19.51 80.326,19.51 79.865,19.05 v1@79.865,16.172 ; 80.968,15.24 80.797,15.24 80.793,15.244 v1@79.865,16.172
  Mid-Layer 1 w0.125: v2(39.95,21.975) v2(39.95,23.975)
  Mid-Layer 2 w0.152: v1(49.75,17.85) 49.75,12.9 52.668,9.982 64.478,9.982 64.794,9.667 68.659,9.667 71.768,12.776 75.903,12.776 76.69,13.564 79.706,13.564 80.086,13.944 80.086,15.951 v1(79.858,16.18)
IMCU_LED: Q2.1 U2.AL29 | length 2
  Top Layer w0.125: U2.AL29@40.839,26.827 41.325,26.341 Q2.1@41.325,25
